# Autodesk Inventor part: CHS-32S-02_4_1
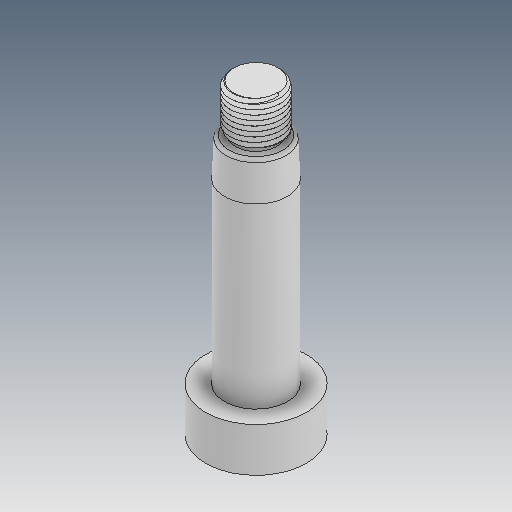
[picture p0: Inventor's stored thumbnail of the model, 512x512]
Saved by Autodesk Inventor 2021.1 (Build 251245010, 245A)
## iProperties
Created: 2021-05
Part Number: CHS-32S-02_4_1
Material: Ogólny
Document SubType Name: Modeling
Designer: user
Density: 1 g/cm^3
Appearance: Domyślna
Author: user
Revision Number: ÈÎºÎ
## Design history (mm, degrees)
feature "ÊäÈë1"
feature "ÊäÈë2"
node "Bryła1"
node "Bryła2"
